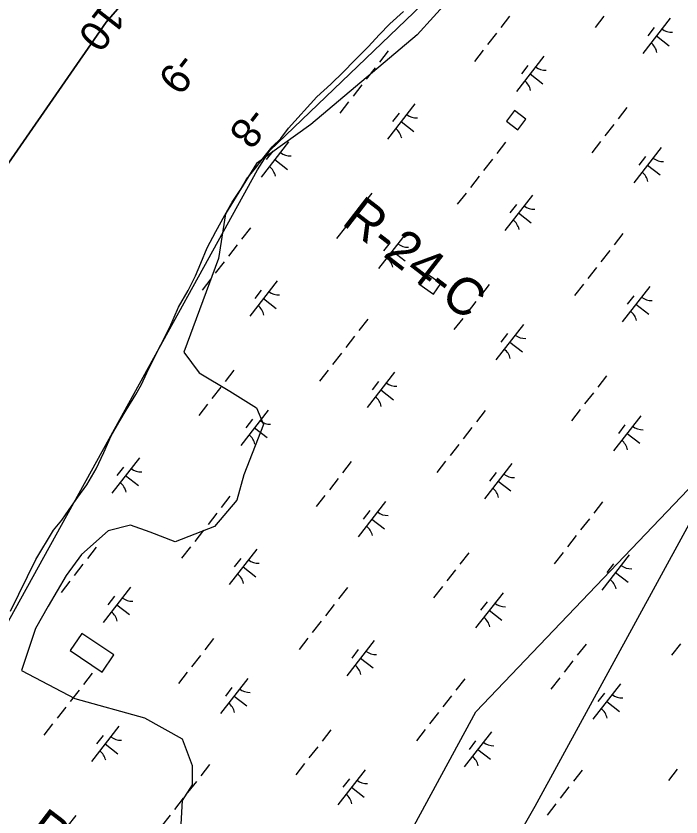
# Model space of a CAD drawing. Extents: x 3888273 to 3909528, y 158682 to 181032.
# Drawn here: x 3903492 to 3904236, y 171905 to 172801 of the extents above; entities that cross this region are included whole.
import ezdxf

# ---------------------------------------------------------------- set-up
doc = ezdxf.new("R2010")
doc.units = 0
for name, color, linetype in [('V-CHAN-DOCK', 7, 'Continuous'), ('V-RIVR-EDGE', 7, 'Continuous'), ('V-RIVR-RANG', 7, 'Continuous'), ('V-RIVR-RANG-IDEN', 7, 'Continuous'), ('V-RRAP-FSHR', 7, 'Continuous'), ('V-TOPO-DPTH', 7, 'Continuous'), ('V-TOPO-MINR', 7, 'Continuous'), ('V-UTIL-LINE', 7, 'Continuous'), ('V-WETL-SWMP', 7, 'Continuous')]:
    doc.layers.add(name, color=color, linetype=linetype)

msp = doc.modelspace()

# ---------------------------------------------------------------- linework, layer by layer
at = {"layer": 'V-CHAN-DOCK'}
for points in [[(3904049.59, 172695.34), (3904040.43, 172683.43), (3904053.18, 172673.62), (3904062.34, 172685.53)], [(3903950.68, 172513.08), (3903942.44, 172501.17), (3903958.92, 172489.77), (3903967.16, 172501.67)], [(3903552.61, 172091.04), (3903588.36, 172066.91), (3903601.25, 172086), (3903565.5, 172110.13)]]:
    msp.add_lwpolyline(points, close=True, dxfattribs=at)
at = {"layer": 'V-RIVR-EDGE'}
msp.add_lwpolyline([(3903995.29, 172840.8), (3903940.58, 172779.84), (3903821.78, 172679.8), (3903760.82, 172636.04), (3903726.44, 172579.76), (3903718.62, 172529.75), (3903679.54, 172425.02), (3903696.74, 172401.57), (3903731.12, 172381.25), (3903760.82, 172362.5), (3903768.64, 172343.74), (3903746.76, 172287.47), (3903738.94, 172259.33), (3903713.93, 172229.63), (3903670.16, 172212.44), (3903642.03, 172223.38), (3903620.15, 172231.2), (3903595.14, 172224.94), (3903565.44, 172198.37), (3903548.24, 172174.92), (3903527.92, 172140.54), (3903513.85, 172115.53), (3903498.22, 172068.63), (3903557.62, 172037.37), (3903635.78, 172015.49), (3903677.98, 171992.04), (3903688.92, 171962.34), (3903688.92, 171940.46), (3903677.98, 171923.27), (3903676.42, 171896.69)], dxfattribs=at)
at = {"layer": 'V-RRAP-FSHR'}
msp.add_lwpolyline([(3902466.35, 170877.42), (3902596.49, 171071.95), (3902658.3, 171152.88), (3902704.71, 171211.92), (3903018.72, 171557.62), (3903166.87, 171672.43), (3903285.59, 171793.84), (3903327.09, 171840.64), (3903602.16, 172338.53), (3903762.13, 172628.87), (3903775.89, 172650.57), (3904124.39, 172985.06), (3904135.77, 173004.73), (3904140.83, 173195.62), (3904143.93, 173228.62), (3904155.6, 173256.29), (3904478.63, 173695.58), (3904503.36, 173734.99), (3904568.38, 173920.22), (3904627.61, 174008.46), (3904693.88, 174118.29), (3904723.89, 174185.44), (3904740.73, 174228.43), (3904769.82, 174250.96)], dxfattribs=at)
at = {"layer": 'V-TOPO-DPTH'}
msp.add_lwpolyline([(3904753.34, 174263.39), (3904639.87, 174067.01), (3904618.4, 174039.19), (3904581.12, 173979.84), (3904522.19, 173904.52), (3904462.83, 173829.53), (3904403.19, 173754.76), (3904119.62, 173401.31), (3904117.47, 173398.63), (3904115.31, 173395.96), (3904113.14, 173393.3), (3904110.97, 173390.63), (3904094.74, 173370.83), (3904084.39, 173358.32), (3904073.96, 173345.87), (3904063.42, 173333.52), (3904052.8, 173321.24), (3903592.8, 172794.07), (3903139.43, 172139.88), (3902765.16, 171401.22)], dxfattribs=at)
at = {"layer": 'V-TOPO-MINR'}
msp.add_lwpolyline([(3902765.16, 171401.22), (3903139.43, 172139.88), (3903592.8, 172794.07), (3904052.8, 173321.24), (3904063.42, 173333.52), (3904073.96, 173345.87), (3904084.39, 173358.32), (3904094.74, 173370.83), (3904110.97, 173390.63), (3904113.14, 173393.3), (3904115.31, 173395.96), (3904117.47, 173398.63), (3904119.62, 173401.31), (3904403.19, 173754.76), (3904462.83, 173829.53), (3904522.19, 173904.52), (3904581.12, 173979.84), (3904618.4, 174039.19), (3904639.87, 174067.01), (3904753.34, 174263.39)], dxfattribs=at)
at = {"layer": 'V-UTIL-LINE'}
for points in [[(3905528.73, 173697.07), (3904376.91, 172459.2), (3904350.43, 172426.1), (3904072.41, 171916.39), (3903483.26, 170883.72), (3902993.41, 170023.17), (3902953.69, 169950.36), (3902854.4, 169652.47), (3902708.76, 169268.53)], [(3902927.21, 169208.96), (3902847.78, 169559.8), (3902827.92, 169778.25), (3902907.35, 170023.17), (3903370.73, 170850.63), (3904006.21, 172022.3), (3904694.65, 172743.84), (3905561.82, 173663.97)]]:
    msp.add_lwpolyline(points, dxfattribs=at)
at = {"layer": 'V-WETL-SWMP'}
for p, q in [((3903910.21, 172792.4), (3903925.34, 172806.27)), ((3904043.97, 172800.77), (3904034.14, 172788.15)), ((3904149.43, 172801.02), (3904139.6, 172788.39)), ((3903898.2, 172780.13), (3903910.21, 172792.4)), ((3904223.57, 172798.54), (3904192.87, 172759.08)), ((3904029.23, 172781.83), (3904019.4, 172769.2)), ((3904205.81, 172788.29), (3904198.45, 172778.81)), ((3903886.2, 172767.08), (3903898.2, 172780.13)), ((3904208.22, 172778.81), (3904222.43, 172767.76)), ((3903870.31, 172750.86), (3903886.2, 172767.08)), ((3903908.26, 172761.92), (3903898.43, 172749.29)), ((3904014.49, 172762.89), (3904004.66, 172750.26)), ((3904082.33, 172756.09), (3904051.63, 172716.63)), ((3903858.29, 172738.59), (3903870.31, 172750.86)), ((3904064.57, 172745.84), (3904057.2, 172736.37)), ((3903843.95, 172724.73), (3903858.29, 172738.59)), ((3903893.52, 172742.98), (3903883.69, 172730.35)), ((3904066.98, 172736.36), (3904081.18, 172725.31)), ((3903828.43, 172710.46), (3903843.95, 172724.73)), ((3903878.78, 172724.04), (3903868.95, 172711.41)), ((3903796.67, 172675.66), (3903828.43, 172710.46)), ((3903864.04, 172705.1), (3903854.22, 172692.47)), ((3903938.18, 172702.62), (3903907.48, 172663.16)), ((3903920.43, 172692.37), (3903913.06, 172682.9)), ((3904175.25, 172698.63), (3904165.42, 172686)), ((3903922.83, 172682.89), (3903937.04, 172671.84)), ((3903788.18, 172663.82), (3903796.67, 172675.66)), ((3904160.51, 172679.69), (3904150.68, 172667.06)), ((3903796.94, 172660.17), (3903766.24, 172620.71)), ((3903778.48, 172654.71), (3903788.18, 172663.82)), ((3904039.54, 172659.78), (3904029.71, 172647.15)), ((3904145.77, 172660.75), (3904135.94, 172648.12)), ((3903769.59, 172643.65), (3903778.48, 172654.71)), ((3903779.19, 172649.92), (3903771.82, 172640.45)), ((3904213.61, 172653.95), (3904182.91, 172614.49)), ((3903759.94, 172630.62), (3903769.59, 172643.65)), ((3903781.59, 172640.44), (3903795.8, 172629.39)), ((3904024.8, 172640.84), (3904014.97, 172628.21)), ((3904195.85, 172643.69), (3904188.48, 172634.22)), ((3903749.88, 172618.38), (3903759.94, 172630.62)), ((3904198.26, 172634.22), (3904212.47, 172623.16)), ((3904010.06, 172621.89), (3904000.23, 172609.27)), ((3903742.57, 172606.16), (3903749.88, 172618.38)), ((3903733.7, 172592.75), (3903742.57, 172606.16)), ((3903889.86, 172602.71), (3903880.03, 172590.08)), ((3903995.32, 172602.95), (3903985.5, 172590.32)), ((3904069.47, 172600.48), (3904038.76, 172561.02)), ((3903725.63, 172578.17), (3903733.7, 172592.75)), ((3904051.71, 172590.22), (3904044.34, 172580.75)), ((3903715.63, 172560.05), (3903725.63, 172578.17)), ((3903875.12, 172583.77), (3903865.3, 172571.14)), ((3904054.11, 172580.75), (3904068.32, 172569.69)), ((3903705.64, 172541.53), (3903715.63, 172560.05)), ((3903754.15, 172563.86), (3903744.32, 172551.23)), ((3903860.38, 172564.83), (3903850.56, 172552.2)), ((3903928.22, 172558.03), (3903897.52, 172518.57)), ((3904170.82, 172557.63), (3904160.99, 172545)), ((3903698.77, 172524.62), (3903705.64, 172541.53)), ((3903739.41, 172544.92), (3903729.59, 172532.29)), ((3903910.47, 172547.77), (3903903.1, 172538.3)), ((3903912.87, 172538.3), (3903927.08, 172527.25)), ((3904156.08, 172538.69), (3904146.25, 172526.06)), ((3903692.65, 172510.46), (3903698.77, 172524.62)), ((3903724.67, 172525.98), (3903714.85, 172513.35)), ((3904141.34, 172519.75), (3904131.52, 172507.12)), ((3903684.6, 172493.92), (3903692.65, 172510.46)), ((3903709.94, 172507.03), (3903700.11, 172494.41)), ((3903784.08, 172504.56), (3903753.37, 172465.1)), ((3904021.14, 172500.57), (3904011.31, 172487.94)), ((3904126.6, 172500.81), (3904116.78, 172488.18)), ((3904200.75, 172498.33), (3904170.04, 172458.87)), ((3903673.83, 172475.4), (3903684.6, 172493.92)), ((3903766.32, 172494.3), (3903758.95, 172484.83)), ((3904182.99, 172488.08), (3904175.62, 172478.61)), ((3903768.73, 172484.83), (3903782.93, 172473.78)), ((3904006.4, 172481.62), (3903996.58, 172469)), ((3904185.39, 172478.6), (3904199.6, 172467.55)), ((3903663.88, 172452.97), (3903673.83, 172475.4)), ((3903885.43, 172461.71), (3903875.6, 172449.09)), ((3903991.66, 172462.68), (3903981.84, 172450.05)), ((3903653.91, 172432.89), (3903663.88, 172452.97)), ((3904059.5, 172455.89), (3904028.8, 172416.42)), ((3903870.69, 172442.77), (3903860.87, 172430.14)), ((3904041.75, 172445.63), (3904034.38, 172436.16)), ((3903646.23, 172417.92), (3903653.91, 172432.89)), ((3904044.15, 172436.15), (3904058.36, 172425.1)), ((3903855.95, 172423.83), (3903846.13, 172411.2)), ((3903638.17, 172401.78), (3903646.23, 172417.92)), ((3903841.22, 172404.89), (3903831.39, 172392.26)), ((3903632.43, 172388.79), (3903638.17, 172401.78)), ((3903735.75, 172404.65), (3903725.93, 172392.02)), ((3903915.36, 172402.42), (3903884.65, 172362.95)), ((3904152.42, 172398.42), (3904142.6, 172385.79)), ((3903625.9, 172377.36), (3903632.43, 172388.79)), ((3903897.6, 172392.16), (3903890.23, 172382.69)), ((3903721.02, 172385.7), (3903711.19, 172373.08)), ((3903900.01, 172382.68), (3903914.21, 172371.63)), ((3904137.68, 172379.48), (3904127.86, 172366.85)), ((3903615.11, 172360.02), (3903625.9, 172377.36)), ((3903706.28, 172366.76), (3903696.45, 172354.13)), ((3904122.94, 172360.54), (3904113.12, 172347.91)), ((3903607.03, 172346.22), (3903615.11, 172360.02)), ((3903774.12, 172359.97), (3903743.41, 172320.5)), ((3904016.71, 172359.57), (3904006.89, 172346.94)), ((3904190.79, 172353.74), (3904160.08, 172314.28)), ((3903598.57, 172331.25), (3903607.03, 172346.22)), ((3903756.36, 172349.71), (3903748.99, 172340.24)), ((3904173.03, 172343.48), (3904165.66, 172334.01)), ((3903758.77, 172340.24), (3903772.97, 172329.18)), ((3904001.97, 172340.63), (3903992.15, 172328)), ((3904175.43, 172334.01), (3904189.64, 172322.96)), ((3903590.15, 172312.75), (3903598.57, 172331.25)), ((3903987.23, 172321.69), (3903977.41, 172309.06)), ((3903581.72, 172294.26), (3903590.15, 172312.75)), ((3903629.97, 172306.5), (3903599.27, 172267.03)), ((3903867.03, 172302.5), (3903857.21, 172289.87)), ((3903972.5, 172302.74), (3903962.67, 172290.12)), ((3904046.64, 172300.27), (3904015.94, 172260.81)), ((3903571.33, 172276.52), (3903581.72, 172294.26)), ((3903612.22, 172296.24), (3903604.85, 172286.77)), ((3904028.88, 172290.01), (3904021.51, 172280.54)), ((3903614.62, 172286.77), (3903628.83, 172275.71)), ((3903852.3, 172283.56), (3903842.47, 172270.93)), ((3904031.29, 172280.54), (3904045.49, 172269.49)), ((3903561.29, 172262.71), (3903571.33, 172276.52)), ((3903551.65, 172248.9), (3903561.29, 172262.71)), ((3903731.32, 172263.65), (3903721.5, 172251.02)), ((3903837.56, 172264.62), (3903827.73, 172251.99)), ((3903905.4, 172257.82), (3903874.69, 172218.36)), ((3904147.99, 172257.42), (3904138.17, 172244.8)), ((3903543.16, 172236.66), (3903551.65, 172248.9)), ((3903716.59, 172244.71), (3903706.76, 172232.08)), ((3903887.64, 172247.56), (3903880.27, 172238.09)), ((3903533.87, 172225.6), (3903543.16, 172236.66)), ((3903890.05, 172238.09), (3903904.25, 172227.04)), ((3904133.25, 172238.48), (3904123.43, 172225.85)), ((3903514.24, 172192.88), (3903533.87, 172225.6)), ((3903701.85, 172225.77), (3903692.02, 172213.14)), ((3904118.52, 172219.54), (3904108.69, 172206.91)), ((3903581.65, 172206.58), (3903571.82, 172193.95)), ((3903687.11, 172206.82), (3903677.28, 172194.2)), ((3903761.25, 172204.35), (3903730.55, 172164.89)), ((3903998.31, 172200.36), (3903988.49, 172187.73)), ((3904103.78, 172200.6), (3904093.95, 172187.97)), ((3903485.86, 172135.01), (3903514.24, 172192.88)), ((3903743.5, 172194.09), (3903736.13, 172184.62)), ((3904177.92, 172198.13), (3904147.22, 172158.66)), ((3903566.91, 172187.64), (3903557.08, 172175.01)), ((3903745.9, 172184.62), (3903760.11, 172173.57)), ((3903983.58, 172181.41), (3903973.75, 172168.79)), ((3904160.16, 172187.87), (3904152.79, 172178.4)), ((3904162.57, 172178.39), (3904176.77, 172167.34)), ((3903552.17, 172168.7), (3903542.35, 172156.07)), ((3903620.01, 172161.9), (3903589.31, 172122.44)), ((3903862.6, 172161.51), (3903852.78, 172148.88)), ((3903968.84, 172162.47), (3903959.01, 172149.85)), ((3904036.68, 172155.68), (3904005.98, 172116.21)), ((3903602.25, 172151.65), (3903594.89, 172142.17)), ((3904018.92, 172145.42), (3904011.55, 172135.95)), ((3903604.66, 172142.17), (3903618.87, 172131.12)), ((3903847.87, 172142.56), (3903838.04, 172129.94)), ((3904021.33, 172135.95), (3904035.53, 172124.89)), ((3903833.13, 172123.62), (3903823.3, 172110.99)), ((3903712.93, 172104.44), (3903703.1, 172091.81)), ((3903818.39, 172104.68), (3903808.57, 172092.05)), ((3903892.53, 172102.21), (3903861.83, 172062.74)), ((3903874.78, 172091.95), (3903867.41, 172082.48)), ((3904129.6, 172098.21), (3904119.77, 172085.58)), ((3904235.06, 172098.45), (3904225.23, 172085.83)), ((3903698.19, 172085.5), (3903688.36, 172072.87)), ((3903877.18, 172082.48), (3903891.39, 172071.42)), ((3904114.86, 172079.27), (3904105.03, 172066.64)), ((3903577.22, 172065.59), (3903567.39, 172052.96)), ((3903683.45, 172066.55), (3903673.63, 172053.93)), ((3903751.29, 172059.76), (3903720.59, 172020.3)), ((3903993.88, 172059.36), (3903984.06, 172046.73)), ((3904100.12, 172060.33), (3904090.29, 172047.7)), ((3903562.48, 172046.64), (3903552.65, 172034.02)), ((3903733.54, 172049.5), (3903726.17, 172040.03)), ((3904167.96, 172053.53), (3904137.26, 172014.07)), ((3903735.94, 172040.03), (3903750.15, 172028.97)), ((3903979.15, 172040.42), (3903969.32, 172027.79)), ((3904150.2, 172043.27), (3904142.83, 172033.8)), ((3904152.61, 172033.8), (3904166.81, 172022.75)), ((3903547.74, 172027.7), (3903537.92, 172015.08)), ((3903964.41, 172021.48), (3903954.58, 172008.85)), ((3903533, 172008.76), (3903523.18, 171996.13)), ((3903607.15, 172006.29), (3903576.44, 171966.83)), ((3903844.21, 172002.29), (3903834.38, 171989.67)), ((3903949.67, 172002.54), (3903939.85, 171989.91)), ((3903589.39, 171996.03), (3903582.02, 171986.56)), ((3904023.81, 172000.06), (3903993.11, 171960.6)), ((3903591.79, 171986.56), (3903606, 171975.5)), ((3904006.06, 171989.8), (3903998.69, 171980.33)), ((3903829.47, 171983.35), (3903819.64, 171970.72)), ((3904008.46, 171980.33), (3904022.67, 171969.28)), ((3903708.5, 171963.44), (3903698.67, 171950.81)), ((3903814.73, 171964.41), (3903804.91, 171951.78)), ((3903882.57, 171957.61), (3903851.87, 171918.15)), ((3904125.17, 171957.22), (3904115.34, 171944.59)), ((3904231.4, 171958.18), (3904221.57, 171945.56)), ((3903693.76, 171944.5), (3903683.93, 171931.87)), ((3903864.82, 171947.36), (3903857.45, 171937.88)), ((3903867.22, 171937.88), (3903881.43, 171926.83)), ((3904110.43, 171938.27), (3904100.6, 171925.65)), ((3903679.02, 171925.56), (3903669.2, 171912.93)), ((3904095.69, 171919.33), (3904085.86, 171906.7)), ((3903558.82, 171906.37), (3903549, 171893.75)), ((3903664.28, 171906.62), (3903654.46, 171893.99))]:
    msp.add_line(p, q, dxfattribs=at)
for centre, start, end in [((3904225.37, 172800.47), 231.34298, 272.88664), ((3904191.44, 172756.87), 11.34298, 52.88663), ((3904084.13, 172758.02), 231.34298, 272.88664), ((3904050.2, 172714.42), 11.34298, 52.88663), ((3903939.98, 172704.55), 231.34298, 272.88664), ((3903906.06, 172660.95), 11.34298, 52.88663), ((3903798.74, 172662.1), 231.34298, 272.88664), ((3904215.41, 172655.87), 231.34298, 272.88664), ((3903764.82, 172618.5), 11.34298, 52.88663), ((3904181.48, 172612.27), 11.34298, 52.88663), ((3904071.26, 172602.4), 231.34298, 272.88664), ((3904037.34, 172558.8), 11.34298, 52.88663), ((3903930.02, 172559.95), 231.34298, 272.88664), ((3903896.1, 172516.35), 11.34298, 52.88663), ((3903785.88, 172506.48), 231.34298, 272.88664), ((3904202.54, 172500.26), 231.34298, 272.88664), ((3903751.95, 172462.88), 11.34298, 52.88663), ((3904168.62, 172456.66), 11.34298, 52.88663), ((3904061.3, 172457.81), 231.34298, 272.88664), ((3904027.38, 172414.21), 11.34298, 52.88663), ((3903917.16, 172404.34), 231.34298, 272.88664), ((3903883.23, 172360.74), 11.34298, 52.88663), ((3903775.91, 172361.89), 231.34298, 272.88664), ((3904192.58, 172355.66), 231.34298, 272.88664), ((3903741.99, 172318.29), 11.34298, 52.88663), ((3904158.66, 172312.06), 11.34298, 52.88663), ((3903631.77, 172308.42), 231.34298, 272.88664), ((3904048.44, 172302.19), 231.34298, 272.88664), ((3903597.85, 172264.82), 11.34298, 52.88663), ((3904014.51, 172258.59), 11.34298, 52.88663), ((3903907.2, 172259.75), 231.34298, 272.88664), ((3903873.27, 172216.14), 11.34298, 52.88663), ((3903763.05, 172206.28), 231.34298, 272.88664), ((3904179.72, 172200.05), 231.34298, 272.88664), ((3903729.13, 172162.67), 11.34298, 52.88663), ((3904145.79, 172156.45), 11.34298, 52.88663), ((3903621.81, 172163.83), 231.34298, 272.88664), ((3904038.48, 172157.6), 231.34298, 272.88664), ((3903587.89, 172120.23), 11.34298, 52.88663), ((3904004.55, 172114), 11.34298, 52.88663), ((3903894.33, 172104.13), 231.34298, 272.88664), ((3903860.41, 172060.53), 11.34298, 52.88663), ((3903753.09, 172061.68), 231.34298, 272.88664), ((3904169.76, 172055.46), 231.34298, 272.88664), ((3903719.17, 172018.08), 11.34298, 52.88663), ((3904135.83, 172011.86), 11.34298, 52.88663), ((3903608.94, 172008.21), 231.34298, 272.88664), ((3904025.61, 172001.99), 231.34298, 272.88664), ((3903575.02, 171964.61), 11.34298, 52.88663), ((3903991.69, 171958.39), 11.34298, 52.88663), ((3903884.37, 171959.54), 231.34298, 272.88664), ((3903850.45, 171915.94), 11.34298, 52.88663)]:
    msp.add_arc(centre, 17.62, start, end, dxfattribs=at)

# ---------------------------------------------------------------- texts
at = {"layer": 'V-RIVR-RANG'}
for s, p in [('-10', (3903599.61, 172830.18)), ('-9', (3903673.76, 172762.61)), ('-8', (3903753.16, 172701.82))]:
    msp.add_text(s, height=33.5, rotation=232.19833, dxfattribs=at).set_placement(p)
at = {"layer": 'V-RIVR-RANG-IDEN'}
for s, rotation, p in [('R-24-C', 322.33545, (3903855.05, 172568.81)), ('R-16-C', 322.65659, (3903500.93, 171883.53))]:
    msp.add_text(s, height=41.5, rotation=rotation, dxfattribs=at).set_placement(p)

doc.saveas('drawing.dxf')
